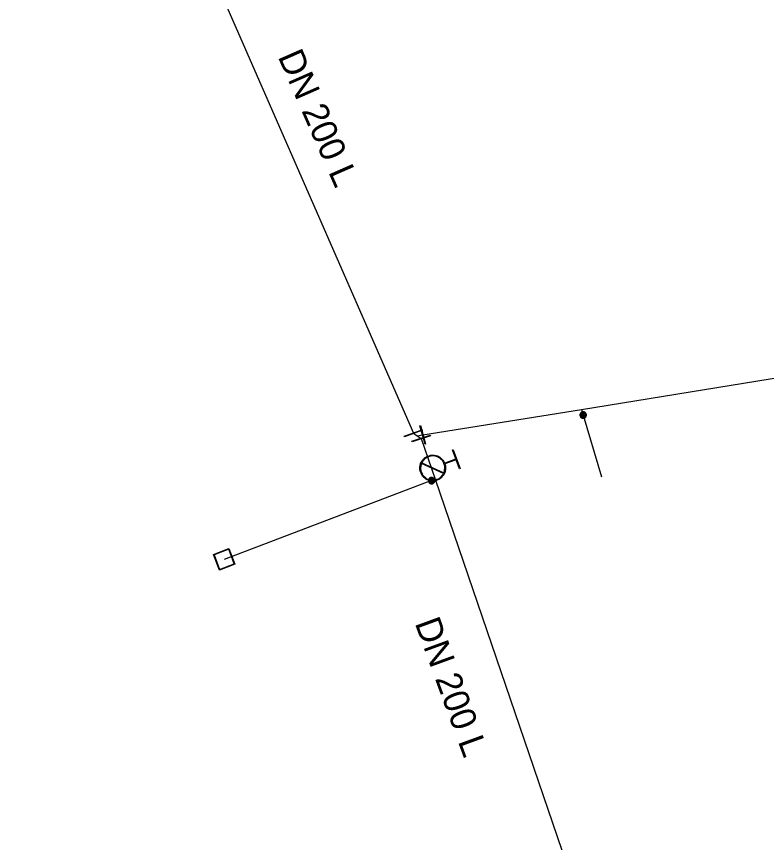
# Model space of a CAD drawing. Extents: x -832382 to -831581, y -1074670 to -1074251.
# Drawn here: x -831742.3 to -831683.8, y -1074434.1 to -1074369.6 of the extents above; entities that cross this region are included whole.
import ezdxf

# ---------------------------------------------------------------- set-up
doc = ezdxf.new("R2010")
doc.units = 0
for name, color, linetype in [('Hyd-odbočka', 7, 'Continuous'), ('Hydrant', 7, 'Continuous'), ('Přípojka vodovodu', 7, 'Continuous'), ('Přípojkový uzávěr', 7, 'Continuous'), ('Roz-řad', 7, 'Continuous'), ('Roz-řad-popis základní', 7, 'Continuous'), ('Řad-šoupě', 7, 'Continuous'), ('Šachta vodovodní', 7, 'Continuous')]:
    doc.layers.add(name, color=color, linetype=linetype)

msp = doc.modelspace()

# ---------------------------------------------------------------- linework, layer by layer
at = {"layer": 'Hyd-odbočka'}
msp.add_line((-831709.84, -1074404.87), (-831709.938, -1074404.913), dxfattribs=at)
at = {"layer": 'Hydrant'}
for points in [[(-831708.914, -1074404.491), (-831708.035, -1074404.164), (-831708.297, -1074403.461), (-831708.239, -1074403.439), (-831707.693, -1074404.904), (-831707.752, -1074404.925), (-831708.014, -1074404.223), (-831708.892, -1074404.55)], [(-831708.998, -1074405.288), (-831710.709, -1074404.508)], [(-831710.682, -1074404.452), (-831708.973, -1074405.233)]]:
    msp.add_lwpolyline(points, dxfattribs=at)
for points in [[(-831708.892, -1074404.55), (-831708.817, -1074404.774), (-831708.852, -1074405.027), (-831708.889, -1074405.295), (-831709.067, -1074405.505), (-831709.246, -1074405.716), (-831709.491, -1074405.807), (-831709.734, -1074405.898), (-831710.003, -1074405.857), (-831710.273, -1074405.817), (-831710.48, -1074405.64), (-831710.686, -1074405.463), (-831710.777, -1074405.219), (-831710.868, -1074404.976), (-831710.827, -1074404.707), (-831710.787, -1074404.437), (-831710.61, -1074404.23), (-831710.433, -1074404.024), (-831710.189, -1074403.933), (-831709.944, -1074403.842), (-831709.672, -1074403.884), (-831709.4, -1074403.926), (-831709.196, -1074404.105), (-831709.004, -1074404.271), (-831708.914, -1074404.491)], [(-831708.973, -1074405.233), (-831708.93, -1074405.129), (-831708.914, -1074405.017), (-831708.879, -1074404.764), (-831708.962, -1074404.543), (-831709.044, -1074404.321), (-831709.236, -1074404.153), (-831709.428, -1074403.985), (-831709.682, -1074403.945), (-831709.937, -1074403.906), (-831710.167, -1074403.992), (-831710.396, -1074404.077), (-831710.561, -1074404.272), (-831710.634, -1074404.355), (-831710.682, -1074404.452)], [(-831710.709, -1074404.508), (-831710.749, -1074404.606), (-831710.764, -1074404.716), (-831710.804, -1074404.969), (-831710.718, -1074405.197), (-831710.633, -1074405.426), (-831710.439, -1074405.592), (-831710.245, -1074405.759), (-831709.993, -1074405.796), (-831709.741, -1074405.834), (-831709.513, -1074405.748), (-831709.282, -1074405.663), (-831709.116, -1074405.465), (-831709.045, -1074405.38), (-831708.998, -1074405.288)]]:
    msp.add_open_spline(points, degree=3, dxfattribs=at)
at = {"layer": 'Přípojka vodovodu'}
for points in [[(-831698.232, -1074400.291), (-831698.098, -1074400.737), (-831696.662, -1074405.548)], [(-831709.653, -1074405.745), (-831709.93, -1074405.85), (-831726.118, -1074411.992)]]:
    msp.add_lwpolyline(points, dxfattribs=at)
at = {"layer": 'Přípojkový uzávěr'}
for points in [[(-831698.099, -1074400.487), (-831698.036, -1074400.487), (-831697.976, -1074400.52), (-831697.916, -1074400.552), (-831697.882, -1074400.612), (-831697.848, -1074400.672), (-831697.848, -1074400.738), (-831697.848, -1074400.802), (-831697.881, -1074400.862), (-831697.914, -1074400.921), (-831697.974, -1074400.954), (-831698.033, -1074400.987), (-831698.099, -1074400.987), (-831698.163, -1074400.987), (-831698.223, -1074400.954), (-831698.282, -1074400.921), (-831698.315, -1074400.862), (-831698.348, -1074400.802), (-831698.348, -1074400.738), (-831698.348, -1074400.672), (-831698.315, -1074400.612), (-831698.281, -1074400.552), (-831698.221, -1074400.52), (-831698.162, -1074400.487), (-831698.099, -1074400.487)], [(-831698.099, -1074400.511), (-831698.156, -1074400.511), (-831698.21, -1074400.54), (-831698.264, -1074400.569), (-831698.294, -1074400.624), (-831698.325, -1074400.678), (-831698.325, -1074400.738), (-831698.325, -1074400.796), (-831698.295, -1074400.85), (-831698.265, -1074400.904), (-831698.211, -1074400.934), (-831698.157, -1074400.964), (-831698.099, -1074400.964), (-831698.039, -1074400.964), (-831697.985, -1074400.934), (-831697.931, -1074400.904), (-831697.902, -1074400.85), (-831697.872, -1074400.796), (-831697.872, -1074400.738), (-831697.872, -1074400.678), (-831697.902, -1074400.624), (-831697.933, -1074400.569), (-831697.987, -1074400.54), (-831698.041, -1074400.511), (-831698.099, -1074400.511)], [(-831698.099, -1074400.528), (-831698.046, -1074400.528), (-831697.996, -1074400.555), (-831697.946, -1074400.582), (-831697.917, -1074400.632), (-831697.889, -1074400.683), (-831697.889, -1074400.738), (-831697.889, -1074400.792), (-831697.916, -1074400.842), (-831697.944, -1074400.892), (-831697.994, -1074400.919), (-831698.044, -1074400.947), (-831698.099, -1074400.947), (-831698.153, -1074400.947), (-831698.203, -1074400.919), (-831698.253, -1074400.892), (-831698.28, -1074400.842), (-831698.308, -1074400.792), (-831698.308, -1074400.738), (-831698.308, -1074400.683), (-831698.28, -1074400.632), (-831698.252, -1074400.582), (-831698.201, -1074400.555), (-831698.151, -1074400.528), (-831698.099, -1074400.528)], [(-831698.099, -1074400.55), (-831698.177, -1074400.55), (-831698.231, -1074400.605), (-831698.286, -1074400.66), (-831698.286, -1074400.738), (-831698.286, -1074400.815), (-831698.231, -1074400.87), (-831698.176, -1074400.925), (-831698.099, -1074400.925), (-831698.021, -1074400.925), (-831697.966, -1074400.87), (-831697.911, -1074400.815), (-831697.911, -1074400.738), (-831697.911, -1074400.66), (-831697.965, -1074400.605), (-831698.02, -1074400.55), (-831698.099, -1074400.55)], [(-831698.099, -1074400.573), (-831698.03, -1074400.573), (-831697.982, -1074400.621), (-831697.935, -1074400.669), (-831697.935, -1074400.737), (-831697.935, -1074400.805), (-831697.983, -1074400.853), (-831698.031, -1074400.901), (-831698.099, -1074400.901), (-831698.167, -1074400.901), (-831698.215, -1074400.853), (-831698.263, -1074400.805), (-831698.263, -1074400.737), (-831698.263, -1074400.669), (-831698.215, -1074400.621), (-831698.167, -1074400.573), (-831698.099, -1074400.573)], [(-831698.099, -1074400.593), (-831698.159, -1074400.593), (-831698.201, -1074400.635), (-831698.243, -1074400.677), (-831698.243, -1074400.737), (-831698.243, -1074400.797), (-831698.201, -1074400.839), (-831698.159, -1074400.881), (-831698.099, -1074400.881), (-831698.039, -1074400.881), (-831697.997, -1074400.839), (-831697.954, -1074400.797), (-831697.954, -1074400.737), (-831697.954, -1074400.677), (-831697.996, -1074400.635), (-831698.038, -1074400.593), (-831698.099, -1074400.593)], [(-831698.099, -1074400.612), (-831698.046, -1074400.612), (-831698.01, -1074400.649), (-831697.973, -1074400.686), (-831697.973, -1074400.738), (-831697.973, -1074400.789), (-831698.01, -1074400.826), (-831698.047, -1074400.862), (-831698.099, -1074400.862), (-831698.15, -1074400.862), (-831698.187, -1074400.826), (-831698.223, -1074400.789), (-831698.223, -1074400.738), (-831698.223, -1074400.686), (-831698.187, -1074400.649), (-831698.151, -1074400.612), (-831698.099, -1074400.612)], [(-831698.099, -1074400.635), (-831698.141, -1074400.635), (-831698.17, -1074400.665), (-831698.2, -1074400.695), (-831698.2, -1074400.737), (-831698.2, -1074400.779), (-831698.17, -1074400.809), (-831698.141, -1074400.839), (-831698.099, -1074400.839), (-831698.057, -1074400.839), (-831698.027, -1074400.809), (-831697.997, -1074400.779), (-831697.997, -1074400.737), (-831697.997, -1074400.695), (-831698.027, -1074400.665), (-831698.056, -1074400.635), (-831698.099, -1074400.635)], [(-831698.099, -1074400.653), (-831698.063, -1074400.653), (-831698.039, -1074400.677), (-831698.014, -1074400.702), (-831698.014, -1074400.737), (-831698.014, -1074400.772), (-831698.039, -1074400.797), (-831698.064, -1074400.821), (-831698.099, -1074400.821), (-831698.134, -1074400.821), (-831698.158, -1074400.797), (-831698.183, -1074400.772), (-831698.183, -1074400.737), (-831698.183, -1074400.702), (-831698.158, -1074400.677), (-831698.134, -1074400.653), (-831698.099, -1074400.653)], [(-831698.099, -1074400.675), (-831698.124, -1074400.675), (-831698.143, -1074400.693), (-831698.161, -1074400.711), (-831698.161, -1074400.737), (-831698.161, -1074400.763), (-831698.142, -1074400.781), (-831698.124, -1074400.8), (-831698.099, -1074400.8), (-831698.072, -1074400.8), (-831698.054, -1074400.781), (-831698.036, -1074400.763), (-831698.036, -1074400.737), (-831698.036, -1074400.711), (-831698.054, -1074400.693), (-831698.072, -1074400.675), (-831698.099, -1074400.675)], [(-831698.099, -1074400.698), (-831698.082, -1074400.698), (-831698.071, -1074400.709), (-831698.059, -1074400.721), (-831698.059, -1074400.737), (-831698.059, -1074400.753), (-831698.071, -1074400.765), (-831698.082, -1074400.776), (-831698.099, -1074400.776), (-831698.115, -1074400.776), (-831698.126, -1074400.765), (-831698.138, -1074400.753), (-831698.138, -1074400.737), (-831698.138, -1074400.721), (-831698.126, -1074400.709), (-831698.115, -1074400.698), (-831698.099, -1074400.698)], [(-831698.099, -1074400.714), (-831698.108, -1074400.714), (-831698.115, -1074400.721), (-831698.122, -1074400.727), (-831698.122, -1074400.737), (-831698.122, -1074400.747), (-831698.115, -1074400.754), (-831698.108, -1074400.761), (-831698.099, -1074400.761), (-831698.089, -1074400.761), (-831698.082, -1074400.754), (-831698.075, -1074400.747), (-831698.075, -1074400.737), (-831698.075, -1074400.727), (-831698.082, -1074400.721), (-831698.089, -1074400.714), (-831698.099, -1074400.714)], [(-831709.93, -1074405.6), (-831709.867, -1074405.6), (-831709.807, -1074405.632), (-831709.748, -1074405.664), (-831709.714, -1074405.725), (-831709.68, -1074405.785), (-831709.68, -1074405.85), (-831709.68, -1074405.915), (-831709.713, -1074405.975), (-831709.746, -1074406.034), (-831709.805, -1074406.067), (-831709.865, -1074406.1), (-831709.93, -1074406.1), (-831709.995, -1074406.1), (-831710.055, -1074406.067), (-831710.114, -1074406.034), (-831710.147, -1074405.975), (-831710.18, -1074405.915), (-831710.18, -1074405.85), (-831710.18, -1074405.785), (-831710.146, -1074405.725), (-831710.113, -1074405.664), (-831710.053, -1074405.632), (-831709.993, -1074405.6), (-831709.93, -1074405.6)], [(-831709.93, -1074405.623), (-831709.987, -1074405.623), (-831710.042, -1074405.653), (-831710.096, -1074405.682), (-831710.126, -1074405.736), (-831710.157, -1074405.791), (-831710.157, -1074405.85), (-831710.157, -1074405.909), (-831710.127, -1074405.963), (-831710.097, -1074406.017), (-831710.043, -1074406.047), (-831709.989, -1074406.077), (-831709.93, -1074406.077), (-831709.871, -1074406.077), (-831709.817, -1074406.047), (-831709.763, -1074406.017), (-831709.733, -1074405.963), (-831709.703, -1074405.909), (-831709.703, -1074405.85), (-831709.703, -1074405.791), (-831709.734, -1074405.736), (-831709.765, -1074405.682), (-831709.819, -1074405.653), (-831709.873, -1074405.623), (-831709.93, -1074405.623)], [(-831709.93, -1074405.641), (-831709.877, -1074405.641), (-831709.827, -1074405.668), (-831709.777, -1074405.694), (-831709.749, -1074405.745), (-831709.721, -1074405.795), (-831709.721, -1074405.85), (-831709.721, -1074405.905), (-831709.748, -1074405.954), (-831709.775, -1074406.004), (-831709.826, -1074406.032), (-831709.876, -1074406.059), (-831709.93, -1074406.059), (-831709.984, -1074406.059), (-831710.034, -1074406.032), (-831710.085, -1074406.004), (-831710.112, -1074405.954), (-831710.139, -1074405.905), (-831710.139, -1074405.85), (-831710.139, -1074405.795), (-831710.111, -1074405.745), (-831710.083, -1074405.694), (-831710.033, -1074405.668), (-831709.983, -1074405.641), (-831709.93, -1074405.641)], [(-831709.93, -1074405.663), (-831710.009, -1074405.663), (-831710.063, -1074405.717), (-831710.118, -1074405.772), (-831710.118, -1074405.85), (-831710.118, -1074405.928), (-831710.063, -1074405.983), (-831710.008, -1074406.038), (-831709.93, -1074406.038), (-831709.852, -1074406.038), (-831709.797, -1074405.983), (-831709.743, -1074405.928), (-831709.743, -1074405.85), (-831709.743, -1074405.772), (-831709.797, -1074405.717), (-831709.852, -1074405.663), (-831709.93, -1074405.663)], [(-831709.93, -1074405.685), (-831709.862, -1074405.685), (-831709.814, -1074405.733), (-831709.766, -1074405.781), (-831709.766, -1074405.85), (-831709.766, -1074405.918), (-831709.814, -1074405.966), (-831709.862, -1074406.014), (-831709.93, -1074406.014), (-831709.999, -1074406.014), (-831710.047, -1074405.966), (-831710.095, -1074405.918), (-831710.095, -1074405.85), (-831710.095, -1074405.781), (-831710.047, -1074405.733), (-831709.999, -1074405.685), (-831709.93, -1074405.685)], [(-831709.93, -1074405.705), (-831709.991, -1074405.705), (-831710.033, -1074405.747), (-831710.075, -1074405.79), (-831710.075, -1074405.85), (-831710.075, -1074405.909), (-831710.033, -1074405.952), (-831709.991, -1074405.994), (-831709.93, -1074405.994), (-831709.871, -1074405.994), (-831709.828, -1074405.952), (-831709.786, -1074405.909), (-831709.786, -1074405.85), (-831709.786, -1074405.79), (-831709.828, -1074405.747), (-831709.87, -1074405.705), (-831709.93, -1074405.705)], [(-831709.93, -1074405.725), (-831709.878, -1074405.725), (-831709.841, -1074405.762), (-831709.805, -1074405.798), (-831709.805, -1074405.85), (-831709.805, -1074405.902), (-831709.842, -1074405.939), (-831709.878, -1074405.975), (-831709.93, -1074405.975), (-831709.982, -1074405.975), (-831710.018, -1074405.939), (-831710.055, -1074405.902), (-831710.055, -1074405.85), (-831710.055, -1074405.798), (-831710.019, -1074405.762), (-831709.982, -1074405.725), (-831709.93, -1074405.725)], [(-831709.93, -1074405.748), (-831709.972, -1074405.748), (-831710.002, -1074405.778), (-831710.032, -1074405.808), (-831710.032, -1074405.85), (-831710.032, -1074405.892), (-831710.002, -1074405.922), (-831709.972, -1074405.951), (-831709.93, -1074405.951), (-831709.888, -1074405.951), (-831709.858, -1074405.922), (-831709.829, -1074405.892), (-831709.829, -1074405.85), (-831709.829, -1074405.808), (-831709.858, -1074405.778), (-831709.888, -1074405.748), (-831709.93, -1074405.748)], [(-831709.93, -1074405.766), (-831709.895, -1074405.766), (-831709.871, -1074405.79), (-831709.846, -1074405.815), (-831709.846, -1074405.85), (-831709.846, -1074405.885), (-831709.871, -1074405.909), (-831709.895, -1074405.934), (-831709.93, -1074405.934), (-831709.965, -1074405.934), (-831709.99, -1074405.909), (-831710.014, -1074405.885), (-831710.014, -1074405.85), (-831710.014, -1074405.815), (-831709.99, -1074405.79), (-831709.965, -1074405.766), (-831709.93, -1074405.766)], [(-831709.93, -1074405.788), (-831709.956, -1074405.788), (-831709.974, -1074405.806), (-831709.993, -1074405.824), (-831709.993, -1074405.85), (-831709.993, -1074405.876), (-831709.974, -1074405.894), (-831709.956, -1074405.913), (-831709.93, -1074405.913), (-831709.904, -1074405.913), (-831709.886, -1074405.894), (-831709.868, -1074405.876), (-831709.868, -1074405.85), (-831709.868, -1074405.824), (-831709.886, -1074405.806), (-831709.904, -1074405.788), (-831709.93, -1074405.788)], [(-831709.93, -1074405.811), (-831709.914, -1074405.811), (-831709.902, -1074405.822), (-831709.891, -1074405.833), (-831709.891, -1074405.85), (-831709.891, -1074405.866), (-831709.902, -1074405.878), (-831709.914, -1074405.889), (-831709.93, -1074405.889), (-831709.946, -1074405.889), (-831709.958, -1074405.878), (-831709.969, -1074405.866), (-831709.969, -1074405.85), (-831709.969, -1074405.833), (-831709.958, -1074405.822), (-831709.946, -1074405.811), (-831709.93, -1074405.811)], [(-831709.93, -1074405.827), (-831709.94, -1074405.827), (-831709.947, -1074405.833), (-831709.954, -1074405.84), (-831709.954, -1074405.85), (-831709.954, -1074405.86), (-831709.947, -1074405.867), (-831709.94, -1074405.873), (-831709.93, -1074405.873), (-831709.92, -1074405.873), (-831709.914, -1074405.867), (-831709.907, -1074405.86), (-831709.907, -1074405.85), (-831709.907, -1074405.84), (-831709.914, -1074405.833), (-831709.92, -1074405.827), (-831709.93, -1074405.827)]]:
    msp.add_open_spline(points, degree=3, dxfattribs=at)
at = {"layer": 'Roz-řad'}
for p, q in [((-831711.35, -1074402.16), (-831711.045, -1074402.365)), ((-831711.045, -1074402.365), (-831710.62, -1074402.29)), ((-831711.045, -1074402.365), (-831710.74, -1074402.57))]:
    msp.add_line(p, q, dxfattribs=at)
for points in [[(-831742.325, -1074282.893), (-831723.12, -1074342.707), (-831719.785, -1074353.381), (-831727.117, -1074366.128), (-831711.35, -1074402.16)], [(-831710.62, -1074402.29), (-831698.232, -1074400.291), (-831677.099, -1074396.881), (-831639.15, -1074390.757), (-831629.267, -1074389.162)], [(-831710.74, -1074402.57), (-831709.938, -1074404.913), (-831709.653, -1074405.745), (-831699.39, -1074435.73)]]:
    msp.add_lwpolyline(points, dxfattribs=at)
at = {"layer": 'Řad-šoupě'}
for points in [[(-831710.798, -1074401.561), (-831710.397, -1074403.006), (-831710.442, -1074403.019), (-831710.843, -1074401.574), (-831710.798, -1074401.561)], [(-831712.063, -1074402.395), (-831710.653, -1074401.881), (-831710.637, -1074401.925), (-831712.047, -1074402.439), (-831712.063, -1074402.395)], [(-831710.02, -1074402.36), (-831711.446, -1074402.825), (-831711.46, -1074402.78), (-831710.034, -1074402.315), (-831710.02, -1074402.36)]]:
    msp.add_lwpolyline(points, dxfattribs=at)
at = {"layer": 'Šachta vodovodní'}
for points in [[(-831725.741, -1074411.154), (-831725.28, -1074412.369), (-831726.495, -1074412.83), (-831726.957, -1074411.615), (-831725.741, -1074411.154)], [(-831726.904, -1074411.638), (-831726.472, -1074412.778), (-831725.332, -1074412.346), (-831725.765, -1074411.206), (-831726.904, -1074411.638)]]:
    msp.add_lwpolyline(points, dxfattribs=at)

# ---------------------------------------------------------------- texts
at = {"layer": 'Roz-řad-popis základní'}
for rotation, p in [(293.68625, (-831721.955, -1074372.77)), (290.07023, (-831711.259, -1074416.957))]:
    msp.add_text('DN 200 L', height=2, rotation=rotation, dxfattribs=at).set_placement(p)

doc.saveas('drawing.dxf')
